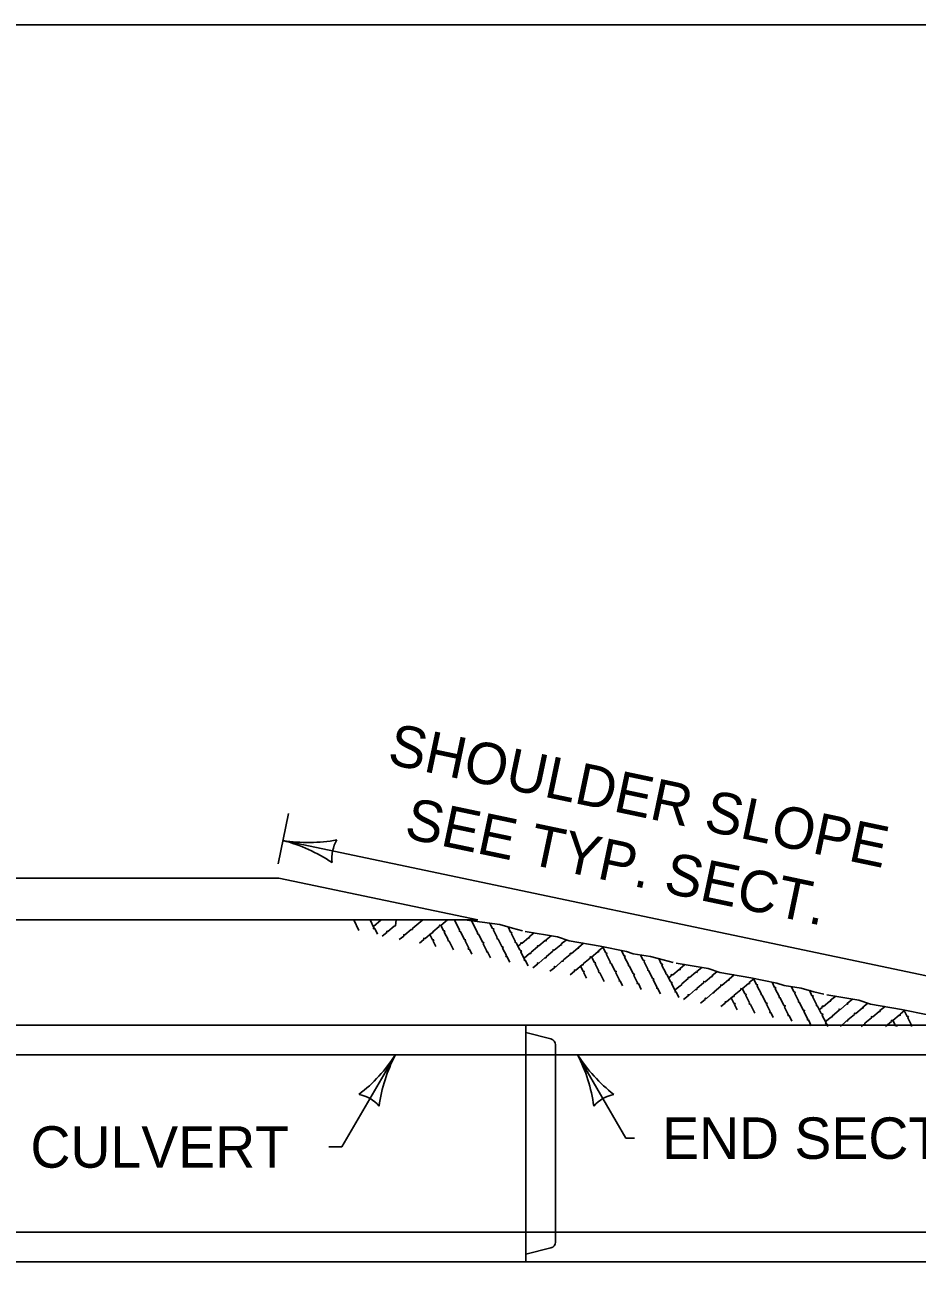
# Model space of a CAD drawing. Extents: x 49991.4 to 50021, y 49987.6 to 50011.4.
# Drawn here: x 50004.56 to 50005.853, y 49997.203 to 49998.999 of the extents above; entities that cross this region are included whole.
import ezdxf

# ---------------------------------------------------------------- set-up
doc = ezdxf.new("R2010")
doc.units = 0
for name, color, linetype in [('Level 1', 7, 'Continuous'), ('Level 2', 7, 'Continuous'), ('Level 3', 7, 'Continuous'), ('Level 4', 7, 'Continuous')]:
    doc.layers.add(name, color=color, linetype=linetype)

msp = doc.modelspace()

# ---------------------------------------------------------------- linework, layer by layer
at = {"layer": 'Level 1'}
for p, q in [((50003.702, 49997.7636), (50004.9281, 49997.7636)), ((50004.9281, 49997.7636), (50005.2161, 49997.7029)), ((50005.2161, 49997.7029), (50003.7019, 49997.7029)), ((50003.702, 49997.5504), (50005.9421, 49997.5504)), ((50005.2857, 49997.5504), (50005.2857, 49997.208)), ((50006.3273, 49997.208), (50003.702, 49997.208))]:
    msp.add_line(p, q, dxfattribs=at)
msp.add_lwpolyline([(49999.3835, 49998.9992), (50016.7501, 49998.9992), (50016.7501, 49987.7988), (49999.3835, 49987.7988)], close=True, dxfattribs=at)
for points in [[(50005.044, 49997.6876), (50005.0367, 49997.7029)], [(50005.0707, 49997.6822), (50005.0668, 49997.6904), (50005.065, 49997.6902), (50005.0657, 49997.6916), (50005.0601, 49997.7029)], [(50005.0762, 49997.7029), (50005.0653, 49997.6936)], [(50005.0978, 49997.7029), (50005.0969, 49997.6942), (50005.095, 49997.694), (50005.086, 49997.6862), (50005.0842, 49997.6865), (50005.0842, 49997.6846), (50005.0776, 49997.6793)], [(50005.1365, 49997.7029), (50005.1219, 49997.691), (50005.1214, 49997.6892), (50005.1197, 49997.6889), (50005.1106, 49997.6812), (50005.1089, 49997.6814), (50005.1089, 49997.6796), (50005.1023, 49997.6745)], [(50005.172, 49997.7029), (50005.1625, 49997.695), (50005.1607, 49997.6955), (50005.1604, 49997.6936), (50005.1511, 49997.6859), (50005.1508, 49997.6841), (50005.1489, 49997.6838), (50005.1399, 49997.6762), (50005.1379, 49997.6763), (50005.1379, 49997.6745), (50005.1316, 49997.6692)], [(50005.1808, 49997.6598), (50005.1745, 49997.6722), (50005.1729, 49997.673), (50005.173, 49997.6746), (50005.1676, 49997.6853), (50005.1682, 49997.6871), (50005.1663, 49997.6874), (50005.1628, 49997.6949)], [(50005.2075, 49997.6532), (50005.2039, 49997.6606), (50005.2024, 49997.6604), (50005.203, 49997.6618), (50005.1976, 49997.6724), (50005.1983, 49997.6742), (50005.1967, 49997.6746), (50005.1913, 49997.6858), (50005.1895, 49997.6865), (50005.1898, 49997.6882), (50005.1822, 49997.7029)], [(50005.1968, 49997.7029), (50005.2479, 49997.6961), (50005.2665, 49997.691), (50005.2807, 49997.6871)], [(50005.2343, 49997.6482), (50005.2303, 49997.6565), (50005.2288, 49997.6565), (50005.2293, 49997.6577), (50005.2239, 49997.6685), (50005.2247, 49997.6703), (50005.2229, 49997.6709), (50005.2174, 49997.6817), (50005.2157, 49997.6826), (50005.2159, 49997.6844), (50005.2064, 49997.7029)], [(50005.2623, 49997.6416), (50005.2583, 49997.6499), (50005.2569, 49997.6499), (50005.2575, 49997.6512), (50005.2519, 49997.6619), (50005.2528, 49997.6636), (50005.251, 49997.6642), (50005.2456, 49997.6752), (50005.2439, 49997.676), (50005.2441, 49997.6776), (50005.2387, 49997.6883), (50005.2393, 49997.6901), (50005.2375, 49997.6904), (50005.2337, 49997.6979)], [(50005.1555, 49997.6646), (50005.1514, 49997.6722), (50005.1523, 49997.6739), (50005.1503, 49997.6742), (50005.1466, 49997.682)], [(50005.2769, 49997.6595), (50005.2719, 49997.6697), (50005.2702, 49997.6706), (50005.2703, 49997.6722), (50005.2648, 49997.6829), (50005.2654, 49997.6846), (50005.2636, 49997.685), (50005.2599, 49997.6928)], [(50005.2979, 49997.6841), (50005.2906, 49997.6782), (50005.2909, 49997.6768), (50005.2894, 49997.6769), (50005.2803, 49997.6692), (50005.2793, 49997.6694)], [(50005.3223, 49997.68), (50005.3149, 49997.6742), (50005.3153, 49997.6726), (50005.3139, 49997.673), (50005.3047, 49997.6652), (50005.3027, 49997.6656), (50005.3027, 49997.6637), (50005.2933, 49997.656), (50005.2929, 49997.6542), (50005.2912, 49997.6541), (50005.2834, 49997.6476)], [(50005.2849, 49997.6862), (50005.3314, 49997.6784), (50005.3485, 49997.6727), (50005.3935, 49997.6649), (50005.4313, 49997.6572), (50005.4413, 49997.6536), (50005.4661, 49997.65), (50005.4847, 49997.6451), (50005.4989, 49997.6412)], [(50005.2792, 49997.6696), (50005.2783, 49997.6697), (50005.278, 49997.6679), (50005.2747, 49997.6649)], [(50005.2889, 49997.6362), (50005.2849, 49997.6445), (50005.2834, 49997.6442), (50005.284, 49997.6457), (50005.2786, 49997.6565), (50005.2793, 49997.6582), (50005.2777, 49997.6588), (50005.2773, 49997.6595)], [(50005.3439, 49997.6738), (50005.3371, 49997.6682), (50005.3374, 49997.6666), (50005.3362, 49997.667), (50005.3269, 49997.6592), (50005.3251, 49997.6596), (50005.3249, 49997.6577), (50005.3155, 49997.65), (50005.3149, 49997.6482), (50005.3133, 49997.6481), (50005.3043, 49997.6403), (50005.3025, 49997.6406), (50005.3025, 49997.6386), (50005.2959, 49997.6334)], [(50005.3693, 49997.6692), (50005.3619, 49997.6632), (50005.3623, 49997.6618), (50005.3609, 49997.662), (50005.3518, 49997.6542), (50005.3499, 49997.6547), (50005.3497, 49997.6529), (50005.3401, 49997.6451), (50005.3398, 49997.6433), (50005.338, 49997.6432), (50005.3289, 49997.6352), (50005.3272, 49997.6356), (50005.3272, 49997.6337), (50005.3206, 49997.6286)], [(50005.3983, 49997.664), (50005.3909, 49997.6582), (50005.3914, 49997.6565), (50005.3899, 49997.6568), (50005.3807, 49997.6492), (50005.3789, 49997.6496), (50005.3788, 49997.6476), (50005.3693, 49997.64), (50005.3689, 49997.638), (50005.3671, 49997.6379), (50005.3581, 49997.6302), (50005.3563, 49997.6304), (50005.3563, 49997.6286), (50005.3499, 49997.6232)], [(50005.4257, 49997.6073), (50005.4223, 49997.6146), (50005.4208, 49997.6145), (50005.4213, 49997.6157), (50005.4159, 49997.6265), (50005.4166, 49997.6283), (50005.4149, 49997.6289), (50005.4094, 49997.6397), (50005.4077, 49997.6406), (50005.4079, 49997.6424), (50005.4025, 49997.6529), (50005.4031, 49997.6546), (50005.4015, 49997.6552), (50005.3977, 49997.6626)], [(50005.4526, 49997.6022), (50005.4487, 49997.6106), (50005.4469, 49997.6106), (50005.4475, 49997.6118), (50005.4421, 49997.6226), (50005.443, 49997.6244), (50005.4412, 49997.625), (50005.4358, 49997.6358), (50005.4343, 49997.6366), (50005.4343, 49997.6385), (50005.4287, 49997.649), (50005.4295, 49997.6506), (50005.4277, 49997.6512), (50005.4241, 49997.6588)], [(50005.3989, 49997.6139), (50005.3927, 49997.6262), (50005.3911, 49997.6271), (50005.3913, 49997.6289), (50005.3859, 49997.6394), (50005.3865, 49997.641), (50005.3845, 49997.6416), (50005.3812, 49997.649)], [(50005.4808, 49997.5958), (50005.4766, 49997.604), (50005.4751, 49997.604), (50005.4757, 49997.6052), (50005.4703, 49997.616), (50005.4709, 49997.6176), (50005.4693, 49997.6182), (50005.4639, 49997.6292), (50005.4622, 49997.6301), (50005.4623, 49997.6318), (50005.4569, 49997.6424), (50005.4574, 49997.644), (50005.4557, 49997.6445), (50005.452, 49997.652)], [(50005.4952, 49997.6136), (50005.4901, 49997.6238), (50005.4885, 49997.6246), (50005.4886, 49997.6265), (50005.4829, 49997.637), (50005.4838, 49997.6386), (50005.4819, 49997.6392), (50005.4781, 49997.6469)], [(50005.5033, 49997.6403), (50005.5498, 49997.6325), (50005.5667, 49997.6268), (50005.6117, 49997.619), (50005.6494, 49997.6112), (50005.6596, 49997.6078), (50005.6843, 49997.6043), (50005.7029, 49997.599), (50005.7172, 49997.5953)], [(50005.3737, 49997.6187), (50005.3698, 49997.6262), (50005.3704, 49997.628), (50005.3686, 49997.6286), (50005.365, 49997.6361)], [(50005.4975, 49997.6236), (50005.4964, 49997.6238), (50005.4964, 49997.622), (50005.4929, 49997.6192)], [(50005.5162, 49997.6382), (50005.5089, 49997.6322), (50005.5093, 49997.6307), (50005.5078, 49997.6312), (50005.4985, 49997.6232), (50005.4976, 49997.6236)], [(50005.5405, 49997.6342), (50005.5333, 49997.6283), (50005.5336, 49997.6268), (50005.5321, 49997.6271), (50005.5229, 49997.6193), (50005.521, 49997.6198), (50005.521, 49997.6181), (50005.5114, 49997.6102), (50005.5111, 49997.6085), (50005.5095, 49997.608), (50005.5019, 49997.6018)], [(50005.5623, 49997.6277), (50005.5555, 49997.6223), (50005.5559, 49997.6208), (50005.5545, 49997.6211), (50005.5453, 49997.6133), (50005.5433, 49997.6138), (50005.5432, 49997.6118), (50005.5337, 49997.6042), (50005.5335, 49997.6022), (50005.5315, 49997.602), (50005.5225, 49997.5944), (50005.5207, 49997.5946), (50005.5207, 49997.5928), (50005.5141, 49997.5875)], [(50005.5876, 49997.6232), (50005.5801, 49997.6172), (50005.5804, 49997.6157), (50005.5792, 49997.6162), (50005.5699, 49997.6082), (50005.5681, 49997.6088), (50005.5679, 49997.607), (50005.5583, 49997.599), (50005.5579, 49997.5974), (50005.5563, 49997.5972), (50005.5473, 49997.5893), (50005.5455, 49997.5898), (50005.5455, 49997.5878), (50005.5389, 49997.5826)], [(50005.5072, 49997.5905), (50005.5033, 49997.5986), (50005.5018, 49997.5986), (50005.5023, 49997.5998), (50005.4969, 49997.6106), (50005.4976, 49997.6122), (50005.4959, 49997.6127), (50005.4955, 49997.6136)], [(50005.6164, 49997.6181), (50005.6093, 49997.6122), (50005.6098, 49997.6108), (50005.6083, 49997.6109), (50005.599, 49997.6032), (50005.5972, 49997.6036), (50005.5969, 49997.6018), (50005.5876, 49997.5941), (50005.5873, 49997.5922), (50005.5855, 49997.592), (50005.5763, 49997.5842), (50005.5744, 49997.5845), (50005.5744, 49997.5826), (50005.5681, 49997.5776)], [(50005.644, 49997.5614), (50005.6404, 49997.5688), (50005.6389, 49997.5688), (50005.6395, 49997.5701), (50005.6341, 49997.5808), (50005.635, 49997.5824), (50005.6332, 49997.583), (50005.6278, 49997.5938), (50005.6263, 49997.5947), (50005.6263, 49997.5965), (50005.6207, 49997.6072), (50005.6213, 49997.6088), (50005.6197, 49997.6092), (50005.6159, 49997.6168)], [(50005.6709, 49997.5563), (50005.6669, 49997.5647), (50005.6653, 49997.5647), (50005.6657, 49997.5659), (50005.6605, 49997.5767), (50005.6613, 49997.5785), (50005.6595, 49997.5791), (50005.6542, 49997.5899), (50005.6524, 49997.5906), (50005.6524, 49997.5926), (50005.647, 49997.6031), (50005.6477, 49997.6049), (50005.6459, 49997.6052), (50005.6423, 49997.6127)], [(50005.6989, 49997.5497), (50005.695, 49997.5581), (50005.6933, 49997.5581), (50005.6939, 49997.5593), (50005.6884, 49997.5701), (50005.6893, 49997.5719), (50005.6875, 49997.5722), (50005.6821, 49997.5833), (50005.6806, 49997.584), (50005.6806, 49997.5857), (50005.6752, 49997.5965), (50005.6759, 49997.5982), (50005.674, 49997.5986), (50005.6704, 49997.6061)], [(50005.5919, 49997.5728), (50005.5879, 49997.5803), (50005.5888, 49997.5821), (50005.5869, 49997.5826), (50005.5833, 49997.59)], [(50005.6173, 49997.568), (50005.611, 49997.5803), (50005.6093, 49997.5812), (50005.6095, 49997.583), (50005.6041, 49997.5936), (50005.6047, 49997.5953), (50005.6029, 49997.5958), (50005.5995, 49997.6031)], [(50005.7135, 49997.5676), (50005.7083, 49997.5779), (50005.7067, 49997.5786), (50005.7069, 49997.5806), (50005.7015, 49997.5911), (50005.7019, 49997.5928), (50005.7001, 49997.5932), (50005.6963, 49997.6012)], [(50005.7345, 49997.5923), (50005.7271, 49997.5866), (50005.7274, 49997.5851), (50005.7262, 49997.5852), (50005.7167, 49997.5776), (50005.7159, 49997.5778)], [(50005.7587, 49997.5882), (50005.7514, 49997.5824), (50005.7519, 49997.5809), (50005.7505, 49997.5812), (50005.7412, 49997.5734), (50005.7393, 49997.5737), (50005.7393, 49997.572), (50005.7298, 49997.5642), (50005.7293, 49997.5626), (50005.7277, 49997.5622), (50005.7199, 49997.5557)], [(50005.7214, 49997.5944), (50005.7679, 49997.5866), (50005.785, 49997.5809), (50005.83, 49997.5731), (50005.8678, 49997.5653), (50005.8779, 49997.5617), (50005.9026, 49997.5584), (50005.9212, 49997.5532), (50005.9355, 49997.5494)], [(50005.7157, 49997.5778), (50005.7148, 49997.5779), (50005.7148, 49997.5761), (50005.7112, 49997.5732)], [(50005.7233, 49997.5486), (50005.7214, 49997.5526), (50005.7199, 49997.5526), (50005.7205, 49997.5539), (50005.7151, 49997.5646), (50005.7159, 49997.5662), (50005.7142, 49997.5668), (50005.7137, 49997.5676)], [(50005.7805, 49997.5818), (50005.7737, 49997.5764), (50005.7742, 49997.5749), (50005.7727, 49997.575), (50005.7634, 49997.5674), (50005.7616, 49997.5677), (50005.7615, 49997.566), (50005.752, 49997.5582), (50005.7517, 49997.5566), (50005.7497, 49997.5562), (50005.7412, 49997.5486)], [(50005.8059, 49997.5773), (50005.7983, 49997.5716), (50005.7988, 49997.5701), (50005.7975, 49997.5702), (50005.7883, 49997.5626), (50005.7863, 49997.5629), (50005.7862, 49997.5611), (50005.7766, 49997.5533), (50005.7765, 49997.5515), (50005.7745, 49997.5512), (50005.7715, 49997.5486)], [(50005.8348, 49997.572), (50005.8276, 49997.5662), (50005.8279, 49997.5647), (50005.8264, 49997.565), (50005.8173, 49997.5572), (50005.8155, 49997.5576), (50005.8153, 49997.556), (50005.8066, 49997.5486)], [(50005.8444, 49997.5486), (50005.8443, 49997.5488), (50005.8444, 49997.5506), (50005.839, 49997.5612), (50005.8397, 49997.5629), (50005.8379, 49997.5632), (50005.8343, 49997.5707)], [(50005.8228, 49997.5486), (50005.8229, 49997.5494), (50005.8213, 49997.5497), (50005.8177, 49997.557)]]:
    msp.add_lwpolyline(points, dxfattribs=at)
at = {"layer": 'Level 2'}
msp.add_line((50016.7501, 49998.9992), (49999.3835, 49998.9992), dxfattribs=at)
at = {"layer": 'Level 3'}
for p, q in [((50004.927, 49997.7841), (50004.9422, 49997.857)), ((50004.9341, 49997.8179), (50005.9533, 49997.6033)), ((50005.0192, 49997.3741), (50005.0967, 49997.5077)), ((50005.4303, 49997.3869), (50005.3606, 49997.5077)), ((50005.0002, 49997.3741), (50005.0192, 49997.3741)), ((50005.4303, 49997.3869), (50005.443, 49997.3869))]:
    msp.add_line(p, q, dxfattribs=at)
for centre, radius, start, end in [((50004.9706, 49998.048), 0.233, 260.9753, 280.2252), ((50004.8795, 49997.6024), 0.2223, 55.604, 75.7875), ((50005.0595, 49997.7916), 0.0548, 150.2868, 186.0092), ((50004.909, 49997.6268), 0.2223, 307.4112, 327.5947), ((50005.3039, 49997.4011), 0.233, 152.7825, 172.0323), ((50005.1636, 49997.4046), 0.2223, 7.435, 27.6185), ((50005.5565, 49997.6339), 0.233, 212.8063, 232.0561), ((50005.0326, 49997.3967), 0.0548, 42.094, 77.8163), ((50005.4247, 49997.3966), 0.0548, 102.1178, 137.8401)]:
    msp.add_arc(centre, radius, start, end, dxfattribs=at)
at = {"layer": 'Level 4'}
for p, q in [((50005.2857, 49997.5397), (50005.3221, 49997.5305)), ((50005.3286, 49997.5221), (50005.3286, 49997.2363)), ((50003.702, 49997.5077), (50005.9483, 49997.5077)), ((50003.702, 49997.2508), (50006.3273, 49997.2508)), ((50005.2857, 49997.2188), (50005.3221, 49997.2279))]:
    msp.add_line(p, q, dxfattribs=at)
for centre, start, end in [((50005.32, 49997.5222), 0, 75.8703), ((50005.32, 49997.2362), 284.1107, 0)]:
    msp.add_arc(centre, 0.00856, start, end, dxfattribs=at)

# ---------------------------------------------------------------- texts
at = {"layer": 'Level 2'}
for s, p in [('SHOULDER SLOPE', (50005.0834, 49997.9294)), ('SEE TYP. SECT.', (50005.108, 49997.822))]:
    msp.add_text(s, height=0.06, rotation=348.1237, dxfattribs=at).set_placement(p)
for s, p in [('END SECTION', (50005.483, 49997.3569)), ('CULVERT', (50004.5682, 49997.3441))]:
    msp.add_text(s, height=0.06, dxfattribs=at).set_placement(p)

doc.saveas('drawing.dxf')
